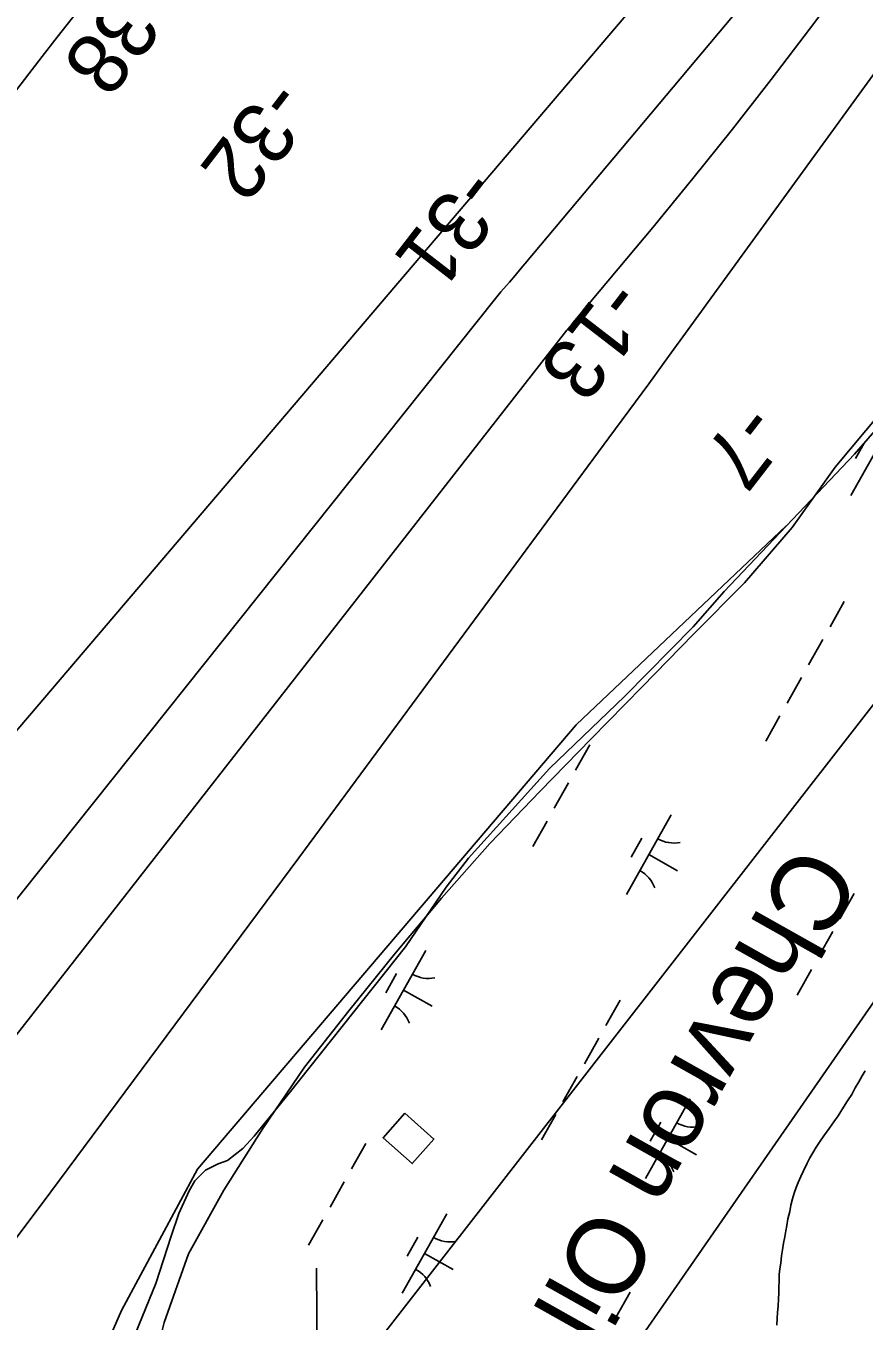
# Model space of a CAD drawing. Extents: x 3913936 to 3933962, y 195330 to 217741.
# Drawn here: x 3923559 to 3924019, y 200928 to 201638 of the extents above; entities that cross this region are included whole.
import ezdxf

# ---------------------------------------------------------------- set-up
doc = ezdxf.new("R2010")
doc.units = 0
for name, color, linetype in [('V-BLDG-IDEN', 7, 'Continuous'), ('V-CHAN-DOCK', 7, 'Continuous'), ('V-RIVR-EDGE', 7, 'Continuous'), ('V-RIVR-RANG', 7, 'Continuous'), ('V-RRAP-FSHR', 7, 'Continuous'), ('V-TOPO-DPTH', 7, 'Continuous'), ('V-TOPO-MINR', 7, 'Continuous'), ('V-TOPO-SHOR', 7, 'Continuous'), ('V-UTIL-LINE', 7, 'Continuous'), ('V-WETL-SWMP', 7, 'Continuous')]:
    doc.layers.add(name, color=color, linetype=linetype)

msp = doc.modelspace()

# ---------------------------------------------------------------- linework, layer by layer
at = {"layer": 'V-CHAN-DOCK'}
msp.add_lwpolyline([(3923766.61, 201041.6), (3923754.66, 201028.16), (3923770.61, 201013.98), (3923782.56, 201027.43)], close=True, dxfattribs=at)
at = {"layer": 'V-RIVR-EDGE'}
msp.add_lwpolyline([(3923975.82, 201363.75), (3923860.64, 201254.69), (3923652.81, 201010.91), (3923611.24, 200933.4), (3923568.55, 200835.66)], dxfattribs=at)
at = {"layer": 'V-RRAP-FSHR'}
msp.add_lwpolyline([(3924094.48, 201469.45), (3924058.51, 201451.58), (3924027.82, 201426.12), (3924002.61, 201395.96), (3923978.96, 201362.84), (3923952.92, 201332.53), (3923924.84, 201304.33), (3923896.77, 201275.54), (3923868.79, 201246.95), (3923840.85, 201218.33), (3923813.16, 201189.47), (3923786.66, 201159.52), (3923760.96, 201128.87), (3923735.86, 201097.73), (3923711.49, 201066.9), (3923688.63, 201033.2), (3923667.27, 200999.38), (3923647.84, 200964.42), (3923634.56, 200926.87), (3923624.89, 200888.1)], dxfattribs=at)
at = {"layer": 'V-TOPO-DPTH'}
for points in [[(3924992.9, 203003.97), (3924555.02, 202345.74), (3924542.66, 202327.33), (3924530.18, 202308.99), (3924517.55, 202290.77), (3924504.81, 202272.62), (3924491.94, 202254.56), (3924479.01, 202236.54), (3924465.99, 202218.59), (3924452.9, 202200.69), (3924405, 202135.5), (3924367.96, 202085.01), (3924330.97, 202034.47), (3924294.08, 201983.86), (3924257.25, 201933.22), (3923922.06, 201471.51), (3923911.22, 201456.61), (3923900.34, 201441.72), (3923889.44, 201426.86), (3923878.5, 201412.02), (3923708.45, 201181.75), (3923640.5, 201090.06), (3923572.36, 200998.52), (3923503.91, 200907.2)], [(3923021.85, 200905.59), (3923325.71, 201305.89), (3923368.53, 201362.16), (3923411.44, 201418.35), (3923454.5, 201474.44), (3923497.65, 201530.45), (3923567.7, 201621.16), (3923575.92, 201631.75), (3923584.16, 201642.31), (3923592.46, 201652.83), (3923600.79, 201663.33), (3923683.12, 201766.64), (3923732.51, 201828.88), (3923781.73, 201891.25), (3923830.7, 201953.81), (3923879.5, 202016.51), (3924180.85, 202405.32), (3924195.7, 202425.15), (3924210.1, 202445.3), (3924223.83, 202465.91), (3924237.1, 202486.83), (3924308.94, 202604.34), (3924356.9, 202684.76), (3924403.67, 202765.84)], [(3923021.85, 200905.59), (3923325.71, 201305.89), (3923368.53, 201362.16), (3923411.44, 201418.35), (3923454.5, 201474.44), (3923497.65, 201530.45), (3923567.7, 201621.16), (3923575.92, 201631.75), (3923584.16, 201642.31), (3923592.46, 201652.83), (3923600.79, 201663.33), (3923683.12, 201766.64), (3923732.51, 201828.88), (3923781.73, 201891.25), (3923830.7, 201953.81), (3923879.5, 202016.51), (3924180.85, 202405.32), (3924195.7, 202425.15), (3924210.1, 202445.3), (3924223.83, 202465.91), (3924237.1, 202486.83), (3924308.94, 202604.34), (3924356.9, 202684.76), (3924403.67, 202765.84)], [(3923130.06, 200754.52), (3923886.98, 201642.64), (3923917.42, 201682.77), (3923947.27, 201723.34), (3923976.75, 201764.19), (3924341.13, 202276.87), (3924356.3, 202298.46), (3924371.3, 202320.16), (3924386.06, 202342.03), (3924400.66, 202364.01), (3924531.02, 202562.63), (3924593.08, 202658.06), (3924654.61, 202753.83)], [(3924654.61, 202753.83), (3924593.08, 202658.06), (3924531.02, 202562.63), (3924400.66, 202364.01), (3924386.06, 202342.03), (3924371.3, 202320.16), (3924356.3, 202298.46), (3924341.13, 202276.87), (3923976.75, 201764.19), (3923947.27, 201723.34), (3923917.42, 201682.77), (3923886.98, 201642.64), (3923130.06, 200754.52)], [(3923353.97, 200902.94), (3923403.94, 200968.88), (3923454.66, 201034.25), (3923505.87, 201099.23), (3923816.26, 201488.45), (3923819.28, 201492.11), (3923822.4, 201495.69), (3923823.98, 201497.46), (3923827.1, 201501.04), (3923828.63, 201502.86), (3923978.81, 201682.18), (3924054.54, 201774.35), (3924129.12, 201867.43), (3924201.96, 201961.88), (3924273.64, 202057.25), (3924414.83, 202248.77), (3924423.58, 202260.78), (3924432.26, 202272.85), (3924440.8, 202285), (3924449.27, 202297.22), (3924696.65, 202658.29), (3924745.15, 202729.8)], [(3924745.15, 202729.8), (3924696.65, 202658.29), (3924449.27, 202297.22), (3924440.8, 202285), (3924432.26, 202272.85), (3924423.58, 202260.78), (3924414.83, 202248.77), (3924273.64, 202057.25), (3924201.96, 201961.88), (3924129.12, 201867.43), (3924054.54, 201774.35), (3923978.81, 201682.18), (3923828.63, 201502.86), (3923827.1, 201501.04), (3923823.98, 201497.46), (3923822.4, 201495.69), (3923819.28, 201492.11), (3923816.26, 201488.45), (3923505.87, 201099.23), (3923454.66, 201034.25), (3923403.94, 200968.88), (3923353.97, 200902.94)]]:
    msp.add_lwpolyline(points, dxfattribs=at)
at = {"layer": 'V-TOPO-MINR'}
for points in [[(3923351.01, 200825.4), (3923855.49, 201471.09), (3923855.91, 201471.62), (3923857.21, 201473.18), (3923858.1, 201474.21), (3923858.54, 201474.73), (3923858.97, 201475.25), (3923902.56, 201527.46), (3923924.57, 201554.26), (3923946.3, 201581.29), (3923967.61, 201608.64), (3923988.63, 201636.23), (3924419.72, 202211.03), (3924436.57, 202233.72), (3924453.27, 202256.52), (3924469.75, 202279.48), (3924486.09, 202302.55), (3924557.12, 202403.88), (3924608.45, 202477.97), (3924659.22, 202552.44), (3924709.16, 202627.47), (3924758.55, 202702.87), (3924974.34, 203036.37)], [(3923503.91, 200907.2), (3923572.36, 200998.52), (3923640.5, 201090.06), (3923708.45, 201181.75), (3923878.5, 201412.02), (3923889.44, 201426.86), (3923900.34, 201441.72), (3923911.22, 201456.61), (3923922.06, 201471.51), (3924257.25, 201933.22), (3924294.08, 201983.86), (3924330.97, 202034.47), (3924367.96, 202085.01), (3924405, 202135.5), (3924452.9, 202200.69), (3924465.99, 202218.59), (3924479.01, 202236.54), (3924491.94, 202254.56), (3924504.81, 202272.62), (3924517.55, 202290.77), (3924530.18, 202308.99), (3924542.66, 202327.33), (3924555.02, 202345.74), (3924992.9, 203003.97)], [(3923021.85, 200905.59), (3923325.71, 201305.89), (3923368.53, 201362.16), (3923411.44, 201418.35), (3923454.5, 201474.44), (3923497.65, 201530.45), (3923567.7, 201621.16), (3923575.92, 201631.75), (3923584.16, 201642.31), (3923592.46, 201652.83), (3923600.79, 201663.33), (3923683.12, 201766.64), (3923732.51, 201828.88), (3923781.73, 201891.25), (3923830.7, 201953.81), (3923879.5, 202016.51), (3924180.85, 202405.32), (3924195.7, 202425.15), (3924210.1, 202445.3), (3924223.83, 202465.91), (3924237.1, 202486.83), (3924308.94, 202604.34), (3924356.9, 202684.76), (3924403.67, 202765.84)], [(3923130.06, 200754.52), (3923886.98, 201642.64), (3923917.42, 201682.77), (3923947.27, 201723.34), (3923976.75, 201764.19), (3924341.13, 202276.87), (3924356.3, 202298.46), (3924371.3, 202320.16), (3924386.06, 202342.03), (3924400.66, 202364.01), (3924531.02, 202562.63), (3924593.08, 202658.06), (3924654.61, 202753.83)], [(3923353.97, 200902.94), (3923403.94, 200968.88), (3923454.66, 201034.25), (3923505.87, 201099.23), (3923816.26, 201488.45), (3923819.28, 201492.11), (3923822.4, 201495.69), (3923823.98, 201497.46), (3923827.1, 201501.04), (3923828.63, 201502.86), (3923978.81, 201682.18), (3924054.54, 201774.35), (3924129.12, 201867.43), (3924201.96, 201961.88), (3924273.64, 202057.25), (3924414.83, 202248.77), (3924423.58, 202260.78), (3924432.26, 202272.85), (3924440.8, 202285), (3924449.27, 202297.22), (3924696.65, 202658.29), (3924745.15, 202729.8)]]:
    msp.add_lwpolyline(points, dxfattribs=at)
at = {"layer": 'V-TOPO-SHOR'}
msp.add_lwpolyline([(3923970.59, 200925.29), (3923970.84, 200929.09), (3923971.01, 200932.12), (3923971.34, 200935.93), (3923971.59, 200939.57), (3923971.67, 200943.03), (3923971.75, 200946.06), (3923972, 200949.6), (3923971.99, 200953.06), (3923972.33, 200956.27), (3923972.75, 200959.38), (3923973.17, 200963.28), (3923973.77, 200966.65), (3923974.28, 200970.29), (3923975.04, 200973.84), (3923975.56, 200977.04), (3923976.15, 200979.98), (3923976.75, 200983.71), (3923977.69, 200987.69), (3923978.37, 200991.07), (3923979.23, 200994.53), (3923980.17, 200997.65), (3923981.2, 201000.76), (3923982.31, 201003.62), (3923983.78, 201006.83), (3923985.33, 201009.95), (3923987.3, 201014.11), (3923988.77, 201017.14), (3923990.41, 201019.82), (3923992.3, 201023.03), (3923994.11, 201025.72), (3923996.43, 201029.18), (3923999.28, 201033.17), (3924001.86, 201036.81), (3924004.28, 201040.19), (3924007.21, 201044.87), (3924009.45, 201048.34), (3924011.69, 201051.89), (3924013.67, 201055.45), (3924015.56, 201058.83), (3924017.46, 201062.03), (3924019, 201064.8)], dxfattribs=at)
at = {"layer": 'V-UTIL-LINE'}
for points in [[(3922259.35, 198607.65), (3922481.8, 198996.51), (3922891.23, 199568.37), (3923401.91, 200205.88), (3924391.34, 201632.88), (3925141.51, 202100.49), (3925635.89, 202689.84), (3926060.57, 203224.55), (3926266.36, 203722.12), (3926398.76, 204373.14), (3926759.45, 205211.96), (3927229.53, 206070.79), (3927602.51, 206766.2), (3928031.78, 207586.17)], [(3924418.51, 201773.34), (3922973.72, 199916.81)], [(3922166.91, 198676.44), (3922606.64, 199354.27), (3923719.03, 200830.83), (3923718.13, 200956.52)]]:
    msp.add_lwpolyline(points, dxfattribs=at)
at = {"layer": 'V-WETL-SWMP'}
for p, q in [((3924035.66, 201423.98), (3924011.16, 201380.39)), ((3924013.18, 201403.14), (3924028.27, 201420.33)), ((3924018.5, 201409.19), (3924013.74, 201400.73)), ((3923941.75, 201327.82), (3924013.18, 201403.14)), ((3923924.77, 201308.41), (3923941.75, 201327.82)), ((3924007.65, 201322.37), (3923999.81, 201308.42)), ((3923887.31, 201270.35), (3923924.77, 201308.41)), ((3923995.89, 201301.45), (3923988.05, 201287.5)), ((3923984.13, 201280.53), (3923976.29, 201266.58)), ((3923845.98, 201230.74), (3923887.31, 201270.35)), ((3923972.37, 201259.61), (3923964.53, 201245.66)), ((3923868.11, 201243.7), (3923860.27, 201229.76)), ((3923801.59, 201181.43), (3923845.98, 201230.74)), ((3923856.35, 201222.78), (3923848.51, 201208.83)), ((3923912.69, 201205.22), (3923888.18, 201161.63)), ((3923844.59, 201201.86), (3923836.75, 201187.91)), ((3923896.65, 201192.44), (3923890.77, 201181.98)), ((3923900.44, 201183.42), (3923916.13, 201174.6)), ((3923789.24, 201165.52), (3923801.59, 201181.43)), ((3923766.87, 201132.93), (3923789.24, 201165.52)), ((3924013.11, 201162.19), (3924005.27, 201148.25)), ((3924001.35, 201141.27), (3923993.51, 201127.32)), ((3923703.2, 201052.59), (3923766.87, 201132.93)), ((3923778.08, 201130.93), (3923753.58, 201087.34)), ((3923762.05, 201118.15), (3923756.17, 201107.69)), ((3923989.59, 201120.35), (3923981.75, 201106.4)), ((3923765.83, 201109.13), (3923781.52, 201100.31)), ((3923884.67, 201103.61), (3923876.83, 201089.67)), ((3923872.91, 201082.69), (3923865.07, 201068.74)), ((3923861.15, 201061.77), (3923853.31, 201047.82)), ((3924017.45, 201062.03), (3924015.56, 201058.83)), ((3924019, 201064.81), (3924017.45, 201062.03)), ((3924013.67, 201055.45), (3924011.69, 201051.89)), ((3924015.56, 201058.83), (3924013.67, 201055.45)), ((3923683.9, 201028.92), (3923703.2, 201052.59)), ((3923923.08, 201049.42), (3923898.58, 201005.83)), ((3924009.45, 201048.34), (3924007.21, 201044.87)), ((3924011.69, 201051.89), (3924009.45, 201048.34)), ((3923849.39, 201040.85), (3923841.55, 201026.9)), ((3924004.28, 201040.19), (3924001.86, 201036.81)), ((3924007.21, 201044.87), (3924004.28, 201040.19)), ((3923907.04, 201036.64), (3923901.16, 201026.18)), ((3923999.28, 201033.17), (3923996.43, 201029.18)), ((3924001.86, 201036.81), (3923999.28, 201033.17)), ((3923677.73, 201022.32), (3923683.9, 201028.92)), ((3923910.83, 201027.63), (3923926.52, 201018.81)), ((3923994.11, 201025.72), (3923992.3, 201023.03)), ((3923996.43, 201029.18), (3923994.11, 201025.72)), ((3923669.23, 201015.71), (3923677.73, 201022.32)), ((3923745.14, 201024.94), (3923737.3, 201011)), ((3923990.4, 201019.82), (3923988.77, 201017.14)), ((3923992.3, 201023.03), (3923990.4, 201019.82)), ((3923657.24, 201010.26), (3923664.2, 201013.76)), ((3923664.2, 201013.76), (3923669.23, 201015.71)), ((3923987.31, 201014.1), (3923985.33, 201009.95)), ((3923988.77, 201017.14), (3923987.31, 201014.1)), ((3923648.36, 200999), (3923651.44, 201004.43)), ((3923651.44, 201004.43), (3923657.24, 201010.26)), ((3923983.78, 201006.83), (3923982.32, 201003.62)), ((3923985.33, 201009.95), (3923983.78, 201006.83)), ((3923642.59, 200986.59), (3923648.36, 200999)), ((3923733.38, 201004.02), (3923725.54, 200990.08)), ((3923980.17, 200997.65), (3923979.23, 200994.53)), ((3923981.2, 201000.76), (3923980.17, 200997.65)), ((3923982.32, 201003.62), (3923981.2, 201000.76)), ((3923978.37, 200991.06), (3923977.69, 200987.69)), ((3923979.23, 200994.53), (3923978.37, 200991.06)), ((3923638.36, 200974.19), (3923642.59, 200986.59)), ((3923721.62, 200983.1), (3923713.77, 200969.15)), ((3923789.71, 200986.46), (3923765.21, 200942.87)), ((3923976.75, 200983.71), (3923976.15, 200979.98)), ((3923977.69, 200987.69), (3923976.75, 200983.71)), ((3923975.56, 200977.04), (3923975.04, 200973.84)), ((3923976.15, 200979.98), (3923975.56, 200977.04)), ((3923629.91, 200948.22), (3923638.36, 200974.19)), ((3923773.68, 200973.68), (3923767.8, 200963.22)), ((3923974.28, 200970.29), (3923973.77, 200966.65)), ((3923975.04, 200973.84), (3923974.28, 200970.29)), ((3923777.46, 200964.67), (3923793.15, 200955.85)), ((3923973.17, 200963.28), (3923972.75, 200959.38)), ((3923973.77, 200966.65), (3923973.17, 200963.28)), ((3923972.33, 200956.27), (3923971.99, 200953.06)), ((3923972.75, 200959.38), (3923972.33, 200956.27)), ((3923608.38, 200895.11), (3923629.91, 200948.22)), ((3923972, 200949.6), (3923971.75, 200946.05)), ((3923971.99, 200953.06), (3923972, 200949.6)), ((3923890.13, 200943.43), (3923882.29, 200929.49)), ((3923971.67, 200943.03), (3923971.59, 200939.57)), ((3923971.75, 200946.05), (3923971.67, 200943.03)), ((3923971.34, 200935.93), (3923971.01, 200932.12)), ((3923971.59, 200939.57), (3923971.34, 200935.93)), ((3923970.84, 200929.1), (3923970.6, 200925.29)), ((3923971.01, 200932.12), (3923970.84, 200929.1))]:
    msp.add_line(p, q, dxfattribs=at)
for centre, start, end in [((3923914.18, 201207.39), 239.88608, 281.42974), ((3923887.11, 201159.23), 19.88608, 61.42973), ((3923779.57, 201133.1), 239.88608, 281.42974), ((3923752.5, 201084.94), 19.88608, 61.42973), ((3923924.57, 201051.59), 239.88608, 281.42974), ((3923897.5, 201003.43), 19.88608, 61.42973), ((3923791.2, 200988.63), 239.88608, 281.42974), ((3923764.13, 200940.47), 19.88608, 61.42973)]:
    msp.add_arc(centre, 17.62, start, end, dxfattribs=at)

# ---------------------------------------------------------------- texts
at = {"layer": 'V-BLDG-IDEN'}
msp.add_text('Chevron Oil Co.', height=41.9999, rotation=240.65788, dxfattribs=at).set_placement((3923980.93, 201191.22))
at = {"layer": 'V-RIVR-RANG'}
for s, rotation, p in [('-38', 232.43814, (3923617.07, 201668.78)), ('-32', 232.43814, (3923692.57, 201610.96)), ('-31', 232.29833, (3923799.47, 201562.28)), ('-13', 232.29833, (3923878.66, 201501.21)), ('-7', 232.29833, (3923952.28, 201432.95))]:
    msp.add_text(s, height=33.5, rotation=rotation, dxfattribs=at).set_placement(p)

doc.saveas('drawing.dxf')
